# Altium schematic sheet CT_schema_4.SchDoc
size 284 x 243 mm
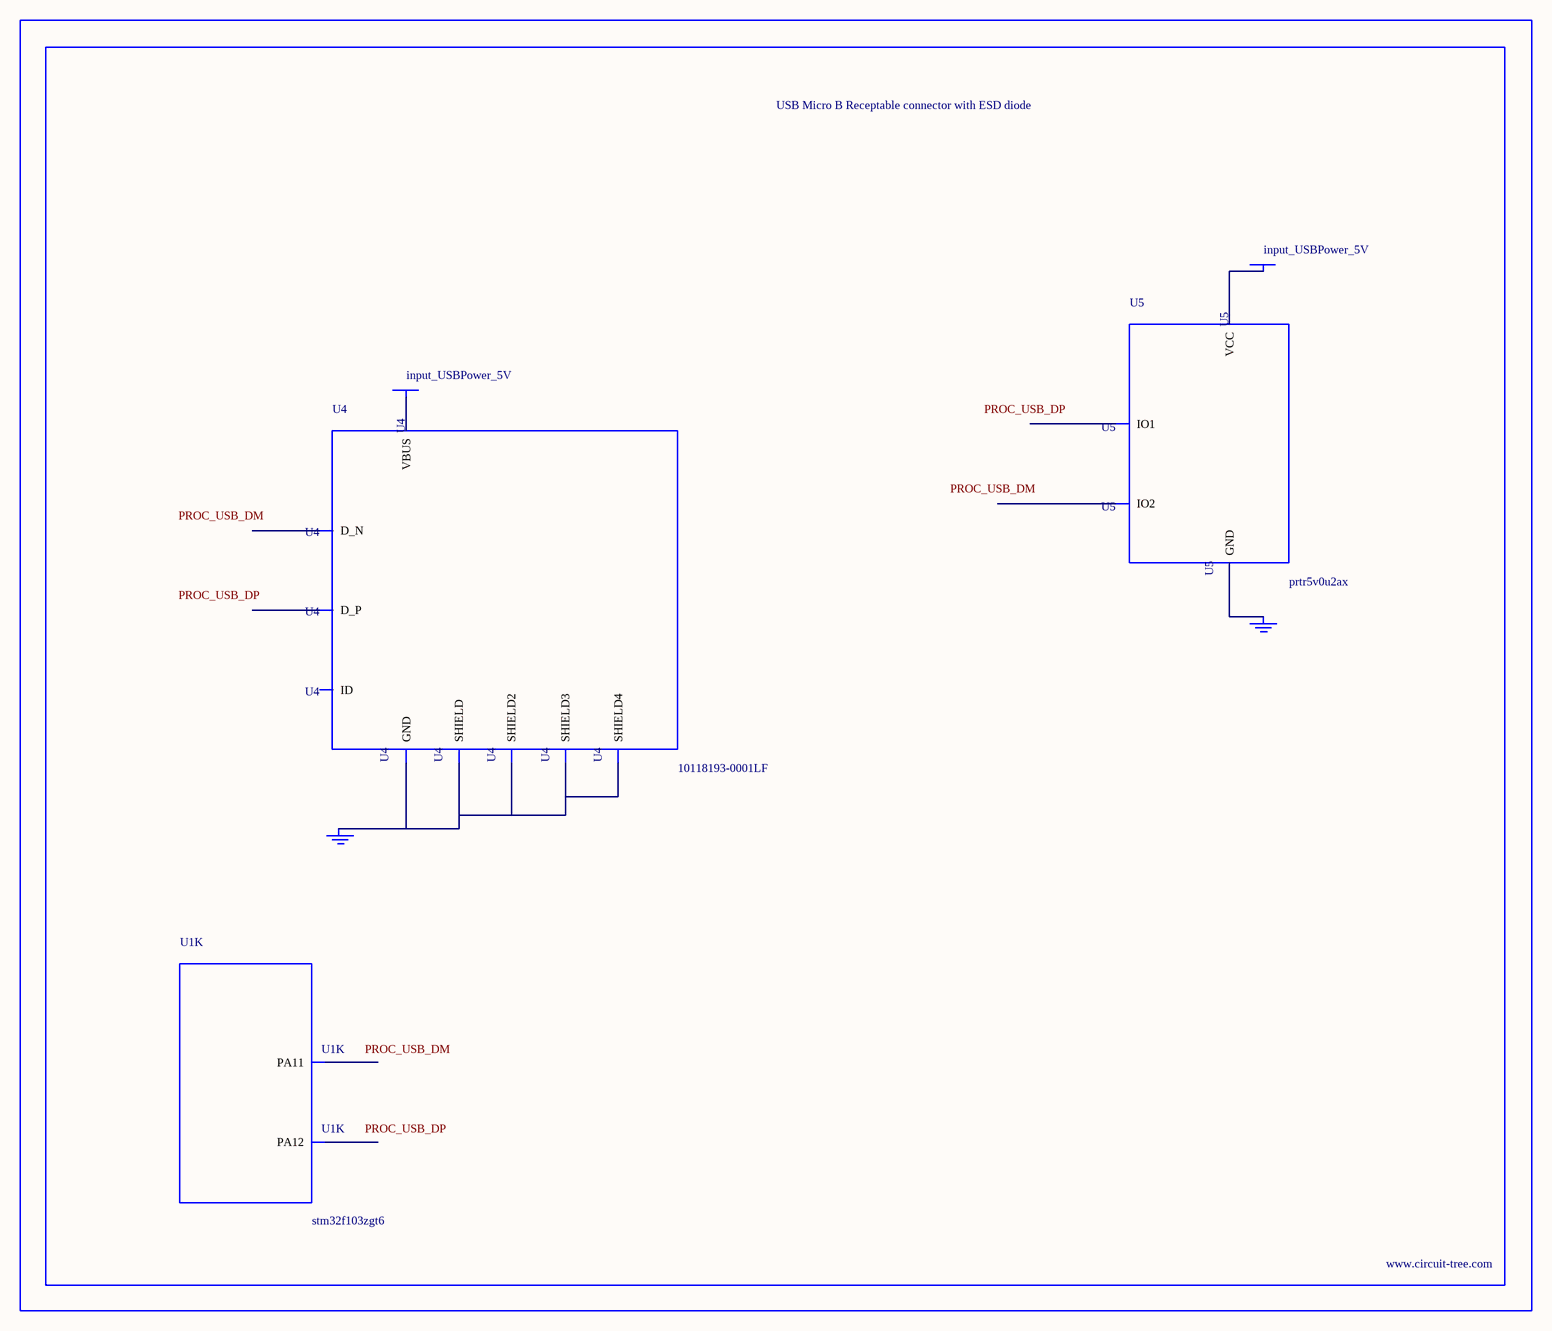
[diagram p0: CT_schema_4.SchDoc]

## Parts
BORDER3  (no value)
GND_INSTANCE_3_0  (no value)
GND_INSTANCE_3_1  (no value)
POWER_INSTANCE_3_0  input_USBPower_5V
POWER_INSTANCE_3_1  input_USBPower_5V
U1  stm32f103zgt6  [LQFP144]  (part K of 12)
U4  10118193-0001LF  [FCI_10118193-0001LF]
U5  prtr5v0u2ax  [SOT143B]

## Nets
NetGND_INSTANCE_3_0_0: GND_INSTANCE_3_0.0(GND) U4.5(GND) U4.6(SHIELD) U4.7(SHIELD2) U4.8(SHIELD3) U4.9(SHIELD4)
NetGND_INSTANCE_3_1_0: GND_INSTANCE_3_1.0(GND) U5.1(GND)
NetPOWER_INSTANCE_3_0_0: POWER_INSTANCE_3_0.0(PWR) U4.1(VBUS)
NetPOWER_INSTANCE_3_1_0: POWER_INSTANCE_3_1.0(PWR) U5.4(VCC)

Not connected (* = marked no-connect by the designer): U1 103(PA11) 104(PA12); U4 2(D_N) 3(D_P) 4(ID); U5 2(IO1) 3(IO2)

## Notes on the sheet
- Labels drawn without touching a wire or pin: PROC_USB_DM, PROC_USB_DP

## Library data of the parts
BORDER3 = BORDER_PAGE3
GND_INSTANCE_3_0 GND_INSTANCE_3_1 = GND
POWER_INSTANCE_3_0 POWER_INSTANCE_3_1 = PWR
